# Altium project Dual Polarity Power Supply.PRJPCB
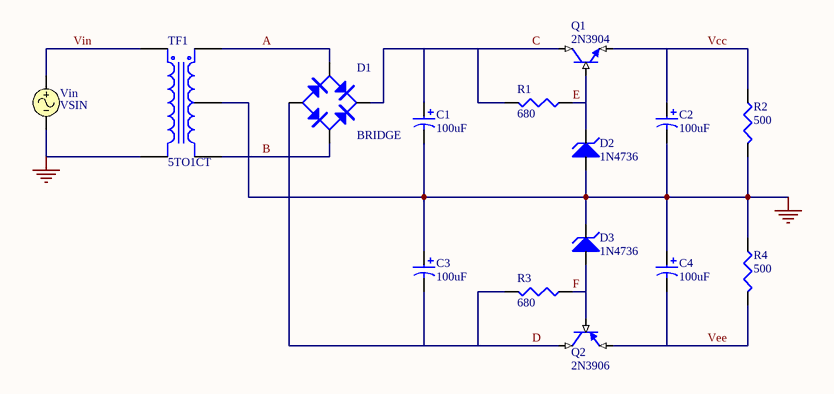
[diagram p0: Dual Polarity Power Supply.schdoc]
1 sheet, 15 parts. Net scope: global (net labels, ports and power ports of the same name join across sheets).

## Sheet Dual Polarity Power Supply.schdoc: Dual Polarity Power Supply
size A4; Organization: Altium Limited; Address1: L3, 12a Rodborough Rd; Address2: Frenchs Forest; Address3: NSW; Address4: Australia 2086; DocumentNumber: 1; SheetNumber: 1; SheetTotal: 1

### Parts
C1  100uF
C2  100uF
C3  100uF
C4  100uF
D1  BRIDGE
D2  1N4736
D3  1N4736
Q1  2N3904
Q2  2N3906
R1  680
R2  500
R3  680
R4  500
TF1  5TO1CT
Vin  VSIN

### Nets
GND: C1.2 C2.2 C3.1 C4.1 D2.1(A) D3.2(K) R2.1(TOP) R4.2(BOT) TF1.2(Pri-) TF1.4(SecCT) Vin.2
A: D1.2(AC) TF1.3(Sec+)
B: D1.4(AC) TF1.5(Sec-)
C: C1.1 D1.3(V+) Q1.1(C) R1.1(TOP)
D: C3.2 D1.1(V-) Q2.1(C) R3.1(TOP)
E: D2.2(K) Q1.2(B) R1.2(BOT)
F: D3.1(A) Q2.2(B) R3.2(BOT)
Vcc: C2.1 Q1.3(E) R2.2(BOT)
Vee: C4.2 Q2.3(E) R4.1(TOP)
Vin: TF1.1(Pri+) Vin.1

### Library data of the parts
C1-C4 = CAP2: Bi-Polar Capacitor
D1 = BRIDGE: Diode Bridge
D2 D3 = 1N4736: Zener Diode
Q1 = 2N3904: NPN BJT
Q2 = 2N3906: PNP BJT
R1-R4 = RES: Resistor
TF1 = 5TO1CT: Center-Tapped Transformer
Vin = VSIN: Sinusoidal Voltage Source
